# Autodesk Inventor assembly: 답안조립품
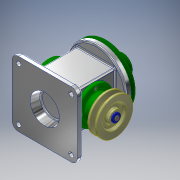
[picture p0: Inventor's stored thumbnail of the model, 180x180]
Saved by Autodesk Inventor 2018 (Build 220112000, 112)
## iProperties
Created: 2021-05
Part Number: 답안조립품
Document SubType Name: Assembly
Designer: theplan76
Author: theplan76
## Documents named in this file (19)
- C:\Users\theplan76\Desktop\710506V1019\답안조립품.iam
- C:\Users\theplan76\Desktop\710506V1019\답안부품.ipt
- C:\Users\theplan76\Desktop\710506V1019\편심축.ipt
- C:\Users\theplan76\Desktop\710506V1019\베어링 17 x 40 x 12.ipt
- C:\Users\theplan76\Desktop\710506V1019\키 4 x 4 x 12.ipt
- C:\Users\theplan76\Desktop\710506V1019\앞커버.ipt
- C:\Users\theplan76\Desktop\710506V1019\오일 실 17 30 8.ipt
- C:\Users\theplan76\Desktop\710506V1019\V-벨트풀리.ipt
- C:\Users\theplan76\Desktop\710506V1019\와셔 4x16.ipt
- C:\Users\theplan76\Desktop\710506V1019\볼트 M4 x 10.ipt
- C:\Users\theplan76\Desktop\710506V1019\뒤커버.ipt
- C:\Users\theplan76\Desktop\710506V1019\볼트 M4 x 12.ipt
- 볼트 M4 x 12.ipt
- C:\Users\theplan76\Desktop\710506V1019\링크.ipt
- C:\Users\theplan76\Desktop\710506V1019\클레비스 핀 6 x 22.ipt
- 클레비스 핀 6 x 22.ipt
- C:\Users\theplan76\Desktop\710506V1019\E-링.ipt
- C:\Users\theplan76\Desktop\710506V1019\슬라이더.ipt
- C:\Users\theplan76\Desktop\710506V1019\덮개.ipt
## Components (2 placed, 2 different names)
1. V-벨트풀리:1
2. E-링:1
